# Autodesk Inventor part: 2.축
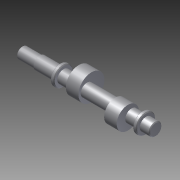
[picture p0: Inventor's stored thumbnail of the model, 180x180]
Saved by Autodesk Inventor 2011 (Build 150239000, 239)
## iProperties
Created: 2015-04
Part Number: 2.축
Document SubType Name: Modeling
Designer: user
Density: 1 g/cm^3
Author: user
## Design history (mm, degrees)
sketch "스케치1"
  geometry: L1 (-90, 0)-(90, 0); L2 (-90, 0)-(-90, 7.5); L3 (-90, 7.5)-(-66, 7.5); L4 (-66, 7.5)-(-66, 8.5); L5 (-66, 8.5)-(-39, 8.5); L6 (-39, 8.5)-(-39, 13); L7 (-39, 13)-(-34, 13); L8 (-34, 13)-(-34, 8.5); L9 (-34, 8.5)-(72, 8.5); L10 (72, 8.5)-(72, 13); L11 (72, 13)-(77, 13); L12 (77, 13)-(77, 8.5); L13 (77, 8.5)-(90, 8.5); L14 (90, 8.5)-(90, 0); 2 further points
  constraints: 28 end point, 11 parallel, 2 perpendicular, 2 vertical alignment, 1 coincident, 1 horizontal, 1 horizontal alignment, 1 midpoint
  dimensions: "d0" = 180 distance of L1.start L1.end; "d1" = 24 distance of L2.end L3.end; "d2" = 27 distance of L4.end L5.end; "d3" = 5 distance of L6.end L7.end; "d4" = 106 distance of L8.end L9.end; "d5" = 5 distance of L10.end L11.end; "d6" = 15 diameter of L3 L1; "d7" = 17 diameter of L5 L1; "d8" = 26 diameter of L7 L1; "d9" = 26 diameter of L11 L1; "d10" = 17 diameter of L9 L1
revolve "회전1" sketch "스케치1" stored, may be unused: angle "d11" = 90 deg
node "작업 평면1"
node "작업 평면2"
sketch "스케치2"
  geometry: L1 (13.54, 6)-(-23.297, 6); C1 r 8.5 at (0, 0) reference; C2 r 8.5 at (0, 0) reference; C3 r 17.5 at (0, 6); 2 further points
  constraints: 2 end point, 1 centre point, 1 coincident, 1 horizontal, 1 point on line
  dimensions: "d14" = 6 distance from line of L1 point (0, 0); "d15" = 35 diameter of C3
extrude "돌출1" join sketch "스케치2" distance "d16" = 17; taper "d17" = 0 deg
node "작업 평면3"
sketch "스케치3"
  geometry: L1 (-8.5, 0)-(8.5, 0); L2 (-8.5, -5)-(8.5, -5); C1 r 15 at (0, -5); A1 r 8.5 centre (0, 0) between (-8.5, 0) and (8.5, 0) reference; 1 further point
  constraints: 4 end point, 2 point on circle, 1 centre point, 1 horizontal, 1 midpoint, 1 parallel
  dimensions: "d19" = 5 distance between parallel lines of L2 L1; "d20" = 30 diameter of C1
extrude "돌출2" join sketch "스케치3" distance "d21" = 17; taper "d22" = 0 deg
chamfer "모따기1" distance "d23" = 1; stored, may be unused: second distance "d24" = 2, angle "d25" = 45 deg
chamfer "모따기2" distance "d26" = 1; stored, may be unused: second distance "d27" = 2, angle "d28" = 45 deg
node "작업 평면4"
sketch "스케치4"
  geometry: L1 (-58.5, -4)-(-58.5, -17.436) reference; L2 (-58.5, -17.436)-(-75.5, -17.436) reference; L3 (-75.5, -17.436)-(-75.5, -4) reference; L4 (-75.5, -4)-(-118.5, -4) reference; L5 (-118.5, -4)-(-118.5, -8.292) reference; L6 (-118.5, -8.292)-(-135.5, -8.292) reference; L7 (-135.5, -8.292)-(-135.5, -4) reference; L8 (-135.5, -4)-(-150, -4) reference; L9 (-150, -4)-(-150, -9.367) reference; L10 (-151, -10.618)-(-154, -10.618) reference; L11 (-155, -9.367)-(-155, -4) reference; L12 (-155, -4)-(-167, -4) reference; L13 (-167, 4)-(-155, 4) reference; L14 (-155, 4)-(-155, 9.367) reference; L15 (-154, 10.618)-(-151, 10.618) reference; L16 (-150, 9.367)-(-150, 4) reference; L17 (-150, 4)-(-135.5, 4) reference; L18 (-135.5, 4)-(-135.5, 8.292) reference; L19 (-135.5, 8.292)-(-118.5, 8.292) reference; L20 (-118.5, 8.292)-(-118.5, 4) reference; L21 (-118.5, 4)-(-75.5, 4) reference; L22 (-75.5, 4)-(-75.5, 17.436) reference; L23 (-75.5, 17.436)-(-58.5, 17.436) reference; L24 (-58.5, 17.436)-(-58.5, 4) reference; L25 (-58.5, 4)-(-44, 4) reference; L26 (-44, 4)-(-44, 9.367) reference; L27 (-43, 10.618)-(-40, 10.618) reference; L28 (-39, 9.367)-(-39, 4) reference; L29 (-39, 4)-(-12, 4) reference; L30 (-12, 4)-(-12, 0) reference; L31 (-12, 0)-(-12, -4) reference; L32 (-12, -4)-(-39, -4) reference; L33 (-39, -4)-(-39, -9.367) reference; L34 (-40, -10.618)-(-43, -10.618) reference; L35 (-44, -9.367)-(-44, -4) reference; L36 (-44, -4)-(-58.5, -4) reference; L37 (11, 0)-(-12, 0) reference; L38 (12.533, -2.5)-(-5.5, -2.5); L39 (-5.5, -2.5)-(-5.5, 2.5); L40 (-5.5, 2.5)-(12.533, 2.5); L41 (12.533, 2.5)-(12.533, -2.5); L42 (11, 0)-(-8, 0); A1 r 2.5 centre (-5.5, 0) between (-5.5, -2.5) and (-8, 0); 3 further points
  constraints: 10 end point, 2 parallel, 2 point on circle, 1 centre point, 1 coincident, 1 horizontal, 1 horizontal alignment, 1 midpoint, 1 perpendicular, 1 point on line, 10 other
  dimensions: "d29" = 5 diameter of A1; "d30" = 19 distance of L37.start L42.end
extrude "돌출3" cut sketch "스케치4" distance "d31" = 3; taper "d32" = 0 deg
node "솔리드1"
node "절단 모서리 투영1"
node "절단 모서리 투영2"
node "절단 모서리 투영3"
node "절단 모서리 투영4"
other parameters: "d12" = 8, "d13" = -70.5, "d18" = -32.5
